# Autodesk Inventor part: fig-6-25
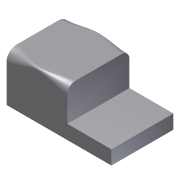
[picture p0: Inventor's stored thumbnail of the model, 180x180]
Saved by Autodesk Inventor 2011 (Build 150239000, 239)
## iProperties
Created: 2004-05
Part Number: fig-6-25
Document SubType Name: Modeling
Designer: CADCIM Technologies
Manufacturer: Standard
Standards Organization: Custom
Density: 1 g/cm^3
Author: CADCIM Technologies
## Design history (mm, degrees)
node "Sketch1"
sketch "Sketch2"
  geometry: L1 (0.098, 47.711)-(0.098, 0.049); L2 (0.098, 0.049)-(-105.483, 0.049); L3 (-105.483, 0.049)-(-105.483, 14.192); L4 (-105.483, 14.192)-(-61.139, 14.192); L5 (-61.139, 14.192)-(-61.139, 47.711); L6 (-61.139, 47.711)-(0.098, 47.711)
  constraints: 12 end point, 3 parallel, 2 perpendicular, 1 vertical
extrude "Extrusion1" new body sketch "Sketch2" stored distance "d0" = 62.5; taper "d1" = 0 deg
fillet "Fillet9" dims "d61" = 10, "d62" = 8, "d63" = 2, "d64" = 5
fillet "Fillet10" dims "d65" = 8, "d66" = 10, "d67" = 2, "d68" = 5
body "Solid1"
